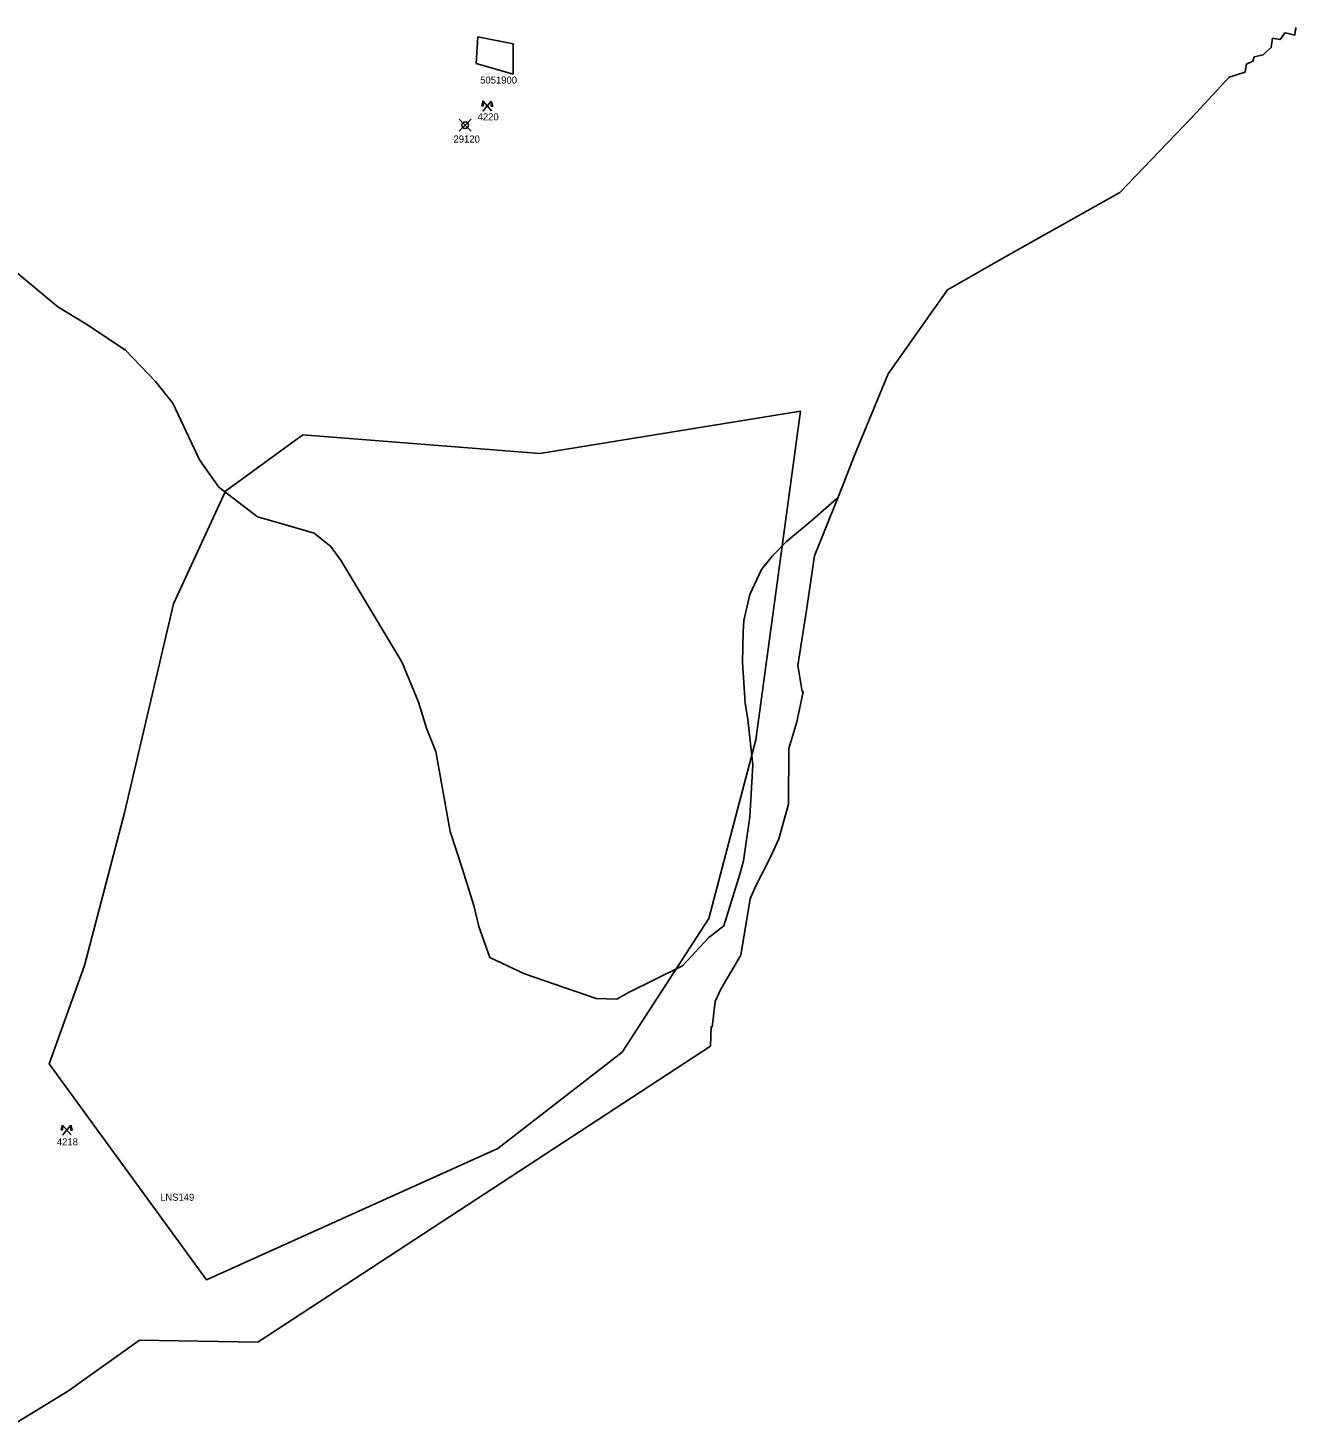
# Model space of a CAD drawing. Extents: x -546762 to -536351, y -1046851 to -1035695.
# Drawn here: x -543000 to -541207, y -1045016 to -1043037 of the extents above; entities that cross this region are included whole.
import ezdxf

# ---------------------------------------------------------------- set-up
doc = ezdxf.new("R2010")
doc.units = 0
for name, color, linetype in [('Vrstva 24', 7, 'Continuous'), ('Vrstva 25', 7, 'Continuous'), ('Vrstva 47', 7, 'Continuous'), ('Vrstva 48', 7, 'Continuous'), ('Vrstva 51', 7, 'Continuous'), ('Vrstva 53', 7, 'Continuous')]:
    doc.layers.add(name, color=color, linetype=linetype)

msp = doc.modelspace()

# ---------------------------------------------------------------- linework, layer by layer
at = {"layer": 'Vrstva 24'}
msp.add_lwpolyline([(-543029.3, -1045016.4), (-542943.2, -1044963.8), (-542842.7, -1044892.1), (-542675.3, -1044895.2), (-542514.6, -1044790), (-542355.2, -1044685.7), (-542194.5, -1044580.5), (-542035.3, -1044476.3), (-542034.3, -1044448.9), (-542032.7, -1044449.4), (-542028.8, -1044413.5), (-542020.4, -1044396.1), (-541992.3, -1044348), (-541979.3, -1044268.3), (-541971.2, -1044249.6), (-541951.2, -1044211.3), (-541938.4, -1044183.3), (-541924.7, -1044134.1), (-541924.6, -1044055.7), (-541913.1, -1044018.1), (-541904.1, -1043975.3), (-541905.8, -1043974.9), (-541911.5, -1043938), (-541899.4, -1043859.9), (-541888, -1043783.2), (-541857.2, -1043706), (-541847.8, -1043682.3), (-541831.9, -1043642.4), (-541783.8, -1043525.8), (-541700.3, -1043407.2), (-541617.6, -1043359.7), (-541456.2, -1043269.3), (-541354.5, -1043163.4), (-541301.7, -1043106.3), (-541295.8, -1043104.4), (-541288.6, -1043102.2), (-541280.7, -1043099.6), (-541279.2, -1043099.1), (-541277.5, -1043089.4), (-541277.2, -1043087.8), (-541269.4, -1043084.4), (-541268.3, -1043083.9), (-541266.4, -1043077.6), (-541253.6, -1043074.6), (-541250.3, -1043071.6), (-541242.2, -1043064.4), (-541241.7, -1043060.7), (-541240.6, -1043051.3), (-541235.7, -1043052.1), (-541229.7, -1043053.1), (-541227.4, -1043049.8), (-541222.9, -1043043.5), (-541218.1, -1043044.6), (-541209.1, -1043046.8), (-541208.2, -1043041.3), (-541207.2, -1043036)], dxfattribs=at)
at = {"layer": 'Vrstva 25'}
msp.add_lwpolyline([(-541856.5, -1043702.1), (-541891.6, -1043732.8), (-541927.6, -1043763.1), (-541947.7, -1043783), (-541963.3, -1043802.7), (-541979.6, -1043837.6), (-541987.9, -1043874.4), (-541988.9, -1043890.7), (-541990, -1043933.5), (-541986.4, -1043991.5), (-541982.4, -1044014.4), (-541975.4, -1044078.9), (-541979.4, -1044152.2), (-541988.5, -1044214.4), (-541993.2, -1044231.7), (-542016.3, -1044306.5), (-542037.8, -1044323), (-542075, -1044363.1), (-542151.1, -1044400.7), (-542167.6, -1044409.8), (-542196.8, -1044409.3), (-542298.2, -1044374.2), (-542347.1, -1044351.1), (-542362.8, -1044307.3), (-542369.7, -1044277.5), (-542386.5, -1044225), (-542403.5, -1044173), (-542423.7, -1044059.7), (-542436.8, -1044026.6), (-542448.1, -1043990), (-542471.1, -1043934.1), (-542557.3, -1043790), (-542572.1, -1043770.1), (-542595.8, -1043751.3), (-542644.1, -1043737.1), (-542676, -1043728), (-542730.6, -1043685.9), (-542757.9, -1043647.3), (-542795.5, -1043567.5), (-542820, -1043536.8), (-542862.5, -1043492.4), (-542918.8, -1043455.3), (-542958.4, -1043431.2), (-543063.6, -1043343.4)], dxfattribs=at)
at = {"layer": 'Vrstva 47'}
msp.add_lwpolyline([(-542364.1, -1043049.3), (-542314.3, -1043059.2), (-542314.3, -1043102), (-542366.4, -1043086.9)], close=True, dxfattribs=at)
at = {"layer": 'Vrstva 48'}
msp.add_lwpolyline([(-542920.5, -1044362.2), (-542970.3, -1044501.6), (-542747.9, -1044807), (-542336.2, -1044621.1), (-542160.3, -1044485), (-542037.5, -1044295.8), (-541971.1, -1044043.5), (-541908, -1043578.7), (-542276.5, -1043638.5), (-542611.8, -1043611.9), (-542721.3, -1043691.6), (-542794.4, -1043850.9), (-542864.1, -1044146.4), (-542920.5, -1044362.2)], dxfattribs=at)
at = {"layer": 'Vrstva 51'}
for p, q in [((-542390.5, -1043182.5), (-542373.9, -1043165.9)), ((-542390.5, -1043165.9), (-542373.9, -1043182.5))]:
    msp.add_line(p, q, dxfattribs=at)
msp.add_circle((-542382.2, -1043174.2), 4.61, dxfattribs=at)
at = {"layer": 'Vrstva 53'}
for p, q in [((-542356.8, -1043140.1), (-542356.8, -1043140.2)), ((-542345.2, -1043140.3), (-542345.2, -1043140.3)), ((-542951.4, -1044588.1), (-542951.4, -1044588.1)), ((-542939.9, -1044588.2), (-542939.9, -1044588.2))]:
    msp.add_line(p, q, dxfattribs=at)
for points in [[(-542356.8, -1043140.2), (-542358.8, -1043147.1), (-542356.8, -1043147.1), (-542356.8, -1043140.1)], [(-542357.1, -1043154.2), (-542345.2, -1043140.3)], [(-542344.9, -1043154), (-542356.8, -1043140.1), (-542356.8, -1043140.2)], [(-542345.2, -1043140.3), (-542343.2, -1043147.3), (-542345.2, -1043147.3), (-542345.2, -1043140.3)], [(-542951.4, -1044588.1), (-542953.4, -1044595), (-542951.4, -1044595), (-542951.4, -1044588.1)], [(-542951.8, -1044602.1), (-542939.9, -1044588.2)], [(-542939.5, -1044601.9), (-542951.4, -1044588.1), (-542951.4, -1044588.1)], [(-542939.9, -1044588.2), (-542937.9, -1044595.2), (-542939.9, -1044595.2), (-542939.9, -1044588.2)]]:
    msp.add_lwpolyline(points, dxfattribs=at)

# ---------------------------------------------------------------- texts
at = {"layer": 'Vrstva 47'}
msp.add_text('5051900', height=10, dxfattribs=at).set_placement((-542360.9, -1043115.4))
at = {"layer": 'Vrstva 48'}
msp.add_text('LNS149', height=10, dxfattribs=at).set_placement((-542813.6, -1044695.1))
at = {"layer": 'Vrstva 51'}
msp.add_text('29120', height=10, dxfattribs=at).set_placement((-542398.6, -1043198.8))
at = {"layer": 'Vrstva 53'}
for s, p in [('4220', (-542364.5, -1043167.4)), ('4218', (-542959.6, -1044616.8))]:
    msp.add_text(s, height=10, dxfattribs=at).set_placement(p)

doc.saveas('drawing.dxf')
